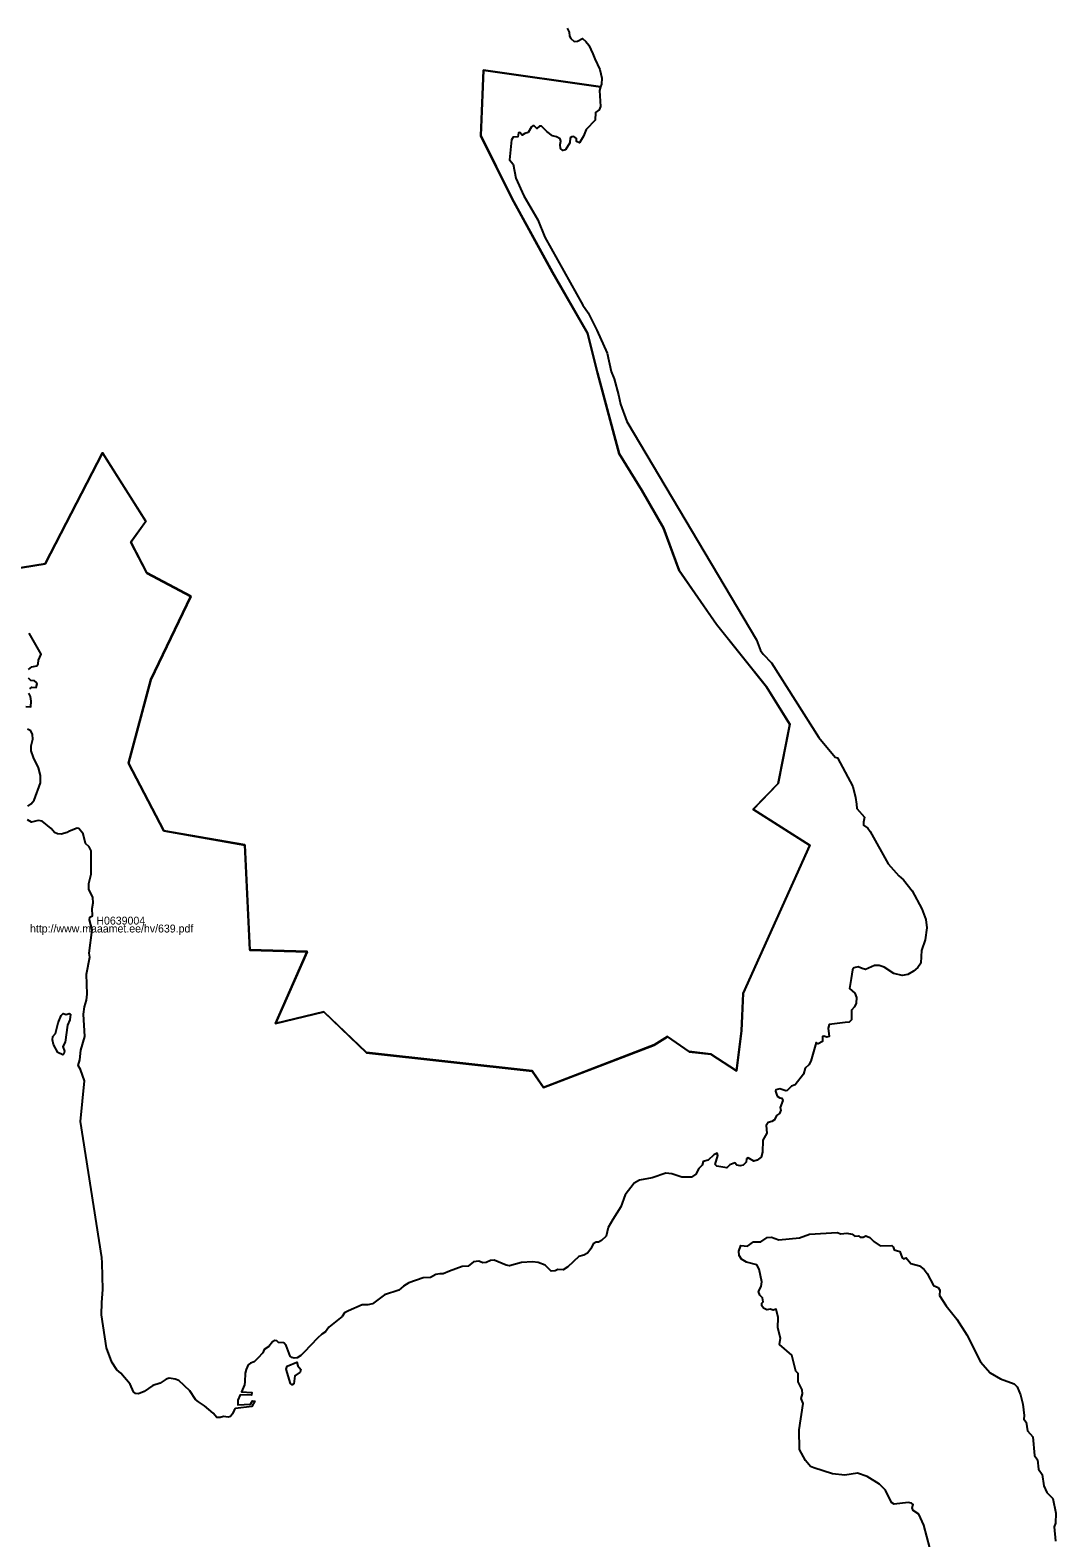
# Model space of a CAD drawing. Extents: x 369010 to 739155, y 6377141 to 6634081.
# Drawn here: x 443413 to 446658, y 6520540 to 6525308 of the extents above; entities that cross this region are included whole.
import ezdxf

# ---------------------------------------------------------------- set-up
doc = ezdxf.new("R2010")
doc.units = 0
for name, color, linetype in [('H_LINK', 7, 'Continuous'), ('H_PIIR', 7, 'Continuous'), ('H_TUNNUS', 7, 'Continuous')]:
    doc.layers.add(name, color=color, linetype=linetype)

msp = doc.modelspace()

# ---------------------------------------------------------------- linework, layer by layer
at = {"layer": 'H_PIIR'}
for points in [[(445111.0814, 6525314.0065), (445117.4214, 6525301.8065), (445118.8915, 6525288.6365), (445122.7913, 6525280.8266), (445133.5214, 6525272.0465), (445144.2615, 6525272.5365), (445159.8715, 6525281.3165), (445171.0914, 6525272.0465), (445179.8714, 6525259.8465), (445192.8015, 6525233.0166), (445198.6514, 6525217.3966), (445214.7514, 6525182.7566), (445221.0915, 6525155.9165), (445220.1214, 6525137.3765), (445217.5751, 6525128.6817), (444846.5215, 6525181.3618), (444838.7514, 6524974.6419), (444936.2714, 6524776.8719), (445065.4214, 6524542.182), (445176.1114, 6524349.6819), (445207.7013, 6524224.5219), (445276.2314, 6523968.732), (445347.3915, 6523852.702), (445415.9113, 6523734.0419), (445465.9914, 6523599.5519), (445584.1214, 6523429.5319), (445742.2614, 6523231.7618), (445816.0514, 6523113.092), (445779.1514, 6522925.8719), (445700.0914, 6522844.122), (445879.3115, 6522730.7319), (445668.8414, 6522262.4918), (445663.5715, 6522143.8319), (445647.7514, 6522017.2518), (445566.0515, 6522069.9919), (445497.5314, 6522077.912), (445429.0014, 6522125.3719), (445386.8314, 6522099.0019), (445036.3013, 6521964.5119), (445000.8414, 6522016.772), (444476.3614, 6522074.7819), (444341.9414, 6522203.9919), (444189.0814, 6522167.0719), (444289.2315, 6522393.8619), (444107.3813, 6522399.1319), (444091.5614, 6522731.3919), (443835.9114, 6522776.2219), (443723.6913, 6522990.3819), (443794.8614, 6523254.0819), (443921.3614, 6523517.7819), (443781.6814, 6523591.6119), (443731.6014, 6523689.1819), (443779.0413, 6523755.1018), (443641.9914, 6523971.3419), (443460.1415, 6523620.6218), (443133.3214, 6523567.8819)], [(443133.29, 6523567.22), (443460.1101, 6523619.9599), (443641.96, 6523970.68), (443779.0099, 6523754.4399), (443731.57, 6523688.52), (443781.65, 6523590.95), (443921.33, 6523517.12), (443794.83, 6523253.42), (443723.6599, 6522989.72), (443835.88, 6522775.56), (444091.53, 6522730.73), (444107.3499, 6522398.47), (444289.2001, 6522393.2), (444189.05, 6522166.41), (444341.91, 6522203.33), (444476.33, 6522074.12), (445000.81, 6522016.1101), (445036.2699, 6521963.85), (445386.8, 6522098.34), (445428.97, 6522124.71), (445497.5, 6522077.2501), (445566.0201, 6522069.33), (445647.72, 6522016.5899), (445663.5401, 6522143.17), (445668.81, 6522261.8299), (445879.2801, 6522730.07), (445700.06, 6522843.4601), (445779.12, 6522925.21), (445816.02, 6523112.4301), (445742.23, 6523231.0999), (445584.09, 6523428.87), (445465.96, 6523598.89), (445415.8799, 6523733.38), (445347.3601, 6523852.0401), (445276.2, 6523968.0701), (445207.6699, 6524223.86), (445176.08, 6524349.02), (445065.39, 6524541.5201), (444936.24, 6524776.21), (444838.72, 6524973.98), (444846.4901, 6525180.6999), (445217.5437, 6525128.0198), (445214.23, 6525116.7046), (445216.67, 6525065.9646), (445213.02, 6525056.2046), (445201.3099, 6525046.9346), (445199.84, 6525022.5446), (445172.04, 6524993.2646), (445163.7399, 6524972.7747), (445150.5701, 6524951.7947), (445141.2999, 6524955.6946), (445141.2999, 6524965.4546), (445132.52, 6524971.3046), (445126.18, 6524970.3347), (445120.81, 6524966.9147), (445119.84, 6524951.7947), (445106.1801, 6524929.3447), (445098.37, 6524927.3946), (445090.0801, 6524933.7346), (445089.1, 6524946.4246), (445092.03, 6524956.1846), (445089.1, 6524964.4746), (445077.64, 6524969.8447), (445064.95, 6524973.2647), (445046.9, 6524987.4146), (445030.32, 6525004.4947), (445024.46, 6525004.0046), (445015.19, 6524996.6846), (445007.3899, 6525004.9847), (445002.51, 6525004.9847), (444998.61, 6525001.5647), (444988.3599, 6524983.9946), (444978.1201, 6524980.5846), (444968.8501, 6524975.2146), (444962.02, 6524983.9946), (444957.63, 6524982.5347), (444955.19, 6524970.8247), (444941.0399, 6524968.8746), (444935.67, 6524960.5747), (444929.33, 6524897.1447), (444941.0399, 6524883.9746), (444949.33, 6524840.0547), (444974.95, 6524783.9447), (445018.85, 6524707.8247), (445040.56, 6524652.6946), (445161.3, 6524437.9946), (445177.6399, 6524413.5947), (445205.4501, 6524359.4347), (445238.62, 6524286.2446), (445251.31, 6524228.1846), (445260.0899, 6524204.7547), (445273.9999, 6524154.9847), (445279.8501, 6524125.2247), (445300.34, 6524070.0846), (445710.38, 6523379.6647), (445723.07, 6523346.4846), (445731.85, 6523334.2846), (445757.7, 6523306.9647), (445907.4799, 6523070.7946), (445959.92, 6523009.3147), (445966.75, 6523006.3847), (446015.5301, 6522915.6247), (446023.34, 6522880.9846), (446026.75, 6522860.0046), (446027.73, 6522846.3346), (446052.61, 6522819.5047), (446049.19, 6522803.3946), (446049.68, 6522793.6446), (446062.8501, 6522784.3646), (446069.93, 6522773.6346), (446127.01, 6522671.1747), (446160.67, 6522633.6047), (446175.54, 6522620.9147), (446202.8599, 6522586.2647), (446233.6001, 6522529.1747), (446246.2801, 6522495.5146), (446249.6999, 6522469.6447), (446244.08, 6522431.1047), (446232.8599, 6522397.4346), (446231.8901, 6522378.8946), (446230.91, 6522357.9147), (446220.67, 6522343.7646), (446207.0101, 6522332.0546), (446189.45, 6522321.8046), (446171.39, 6522318.3846), (446145.54, 6522324.7346), (446114.8001, 6522344.7346), (446098.4599, 6522350.1046), (446084.31, 6522349.6147), (446055.04, 6522337.9046), (446044.7899, 6522340.3446), (446032.6, 6522346.1947), (446018.9401, 6522342.7847), (446014.55, 6522336.9247), (446010.1599, 6522309.1146), (446004.79, 6522277.8846), (446021.38, 6522262.7546), (446026.74, 6522248.6046), (446026.02, 6522230.5546), (446020.6501, 6522219.3347), (446010.8901, 6522208.5946), (446011.3799, 6522178.3447), (446004.06, 6522170.5346), (445990.89, 6522169.5646), (445940.16, 6522163.7046), (445937.23, 6522152.4847), (445940.16, 6522126.1346), (445932.8399, 6522123.6946), (445923.57, 6522126.6246), (445919.6701, 6522125.1647), (445919.6701, 6522110.0346), (445905.52, 6522102.7147), (445899.66, 6522106.6146), (445882.59, 6522048.0647), (445876.4901, 6522036.3547), (445864.7799, 6522025.1346), (445859.42, 6522006.1046), (445832.5901, 6521972.9247), (445821.36, 6521968.5346), (445807.6999, 6521954.8646), (445803.31, 6521953.8947), (445784.29, 6521960.2347), (445772.09, 6521956.8247), (445770.63, 6521952.9146), (445776.4799, 6521937.3047), (445784.29, 6521931.9347), (445791.1201, 6521930.4746), (445793.56, 6521923.1546), (445785.95, 6521900.9247), (445787.96, 6521892.2447), (445783.73, 6521882.2346), (445774.1699, 6521875.3447), (445767.2699, 6521861.7746), (445759.14, 6521856.4347), (445747.58, 6521853.3146), (445741.13, 6521843.9746), (445743.1301, 6521820.1747), (445730.57, 6521798.1447), (445730.12, 6521760.1047), (445725.9001, 6521744.3146), (445712.78, 6521734.5246), (445702.0999, 6521731.8547), (445683.86, 6521742.0847), (445679.19, 6521738.5246), (445678.08, 6521728.2947), (445668.96, 6521719.1747), (445658.8399, 6521716.7247), (445647.9401, 6521718.7346), (445641.71, 6521726.5147), (445626.14, 6521719.3946), (445617.02, 6521710.2746), (445584.65, 6521715.3946), (445579.98, 6521721.3947), (445588.65, 6521748.9847), (445586.2101, 6521756.7646), (445575.53, 6521751.8747), (445557.2899, 6521734.7447), (445542.3901, 6521730.2946), (445539.16, 6521718.7246), (445528.04, 6521707.8246), (445518.25, 6521690.6947), (445505.13, 6521681.1247), (445473.87, 6521680.6846), (445442.73, 6521691.5846), (445424.0501, 6521693.5847), (445380.33, 6521678.6847), (445340.19, 6521671.7947), (445323.7401, 6521662.0047), (445295.4901, 6521624.6346), (445281.14, 6521587.4847), (445255.5599, 6521546.9946), (445241.2201, 6521521.6347), (445234.55, 6521494.4946), (445220.09, 6521480.4746), (445210.5299, 6521475.3646), (445203.41, 6521475.1447), (445193.52, 6521469.8047), (445186.18, 6521454.2247), (445176.17, 6521440.8847), (445164.16, 6521433.9847), (445148.1399, 6521429.7546), (445114.2201, 6521397.0547), (445098.6501, 6521388.1546), (445082.09, 6521389.0447), (445073.41, 6521384.1546), (445060.5099, 6521383.7046), (445041.83, 6521402.8347), (445020.2501, 6521410.8446), (445001.6799, 6521413.2947), (444967.2, 6521411.5147), (444929.27, 6521400.6047), (444918.82, 6521402.1646), (444880.9, 6521418.1746), (444869.11, 6521416.8447), (444855.54, 6521410.6146), (444844.8701, 6521410.3947), (444831.74, 6521415.5147), (444815.4001, 6521412.8446), (444798.0501, 6521399.0446), (444779.5901, 6521398.6046), (444739.44, 6521383.7046), (444718.9801, 6521375.4646), (444708.75, 6521375.4646), (444696.3999, 6521373.0147), (444679.5, 6521363.4546), (444656.37, 6521362.5647), (444610.88, 6521346.9947), (444593.53, 6521336.3146), (444578.63, 6521323.8647), (444533.59, 6521309.1746), (444495.45, 6521280.0347), (444480.99, 6521276.6946), (444462.7499, 6521277.1447), (444420.27, 6521258.6847), (444407.4801, 6521251.3346), (444399.47, 6521239.9946), (444357.0999, 6521206.8447), (444346.8701, 6521192.1646), (444335.7499, 6521184.6046), (444322.18, 6521171.9246), (444279.59, 6521126.9947), (444269.36, 6521116.5346), (444257.3499, 6521109.6446), (444248.01, 6521108.3046), (444240.6701, 6521110.5346), (444235.66, 6521114.9847), (444222.3101, 6521148.7946), (444215.42, 6521157.4746), (444197.8499, 6521158.1347), (444192.7299, 6521162.8147), (444187.17, 6521163.9247), (444179.05, 6521160.1346), (444167.4801, 6521145.0147), (444153.0301, 6521136.3347), (444148.3601, 6521125.8747), (444133.2299, 6521108.0847), (444121.44, 6521096.9646), (444110.1, 6521092.9547), (444102.43, 6521086.9446), (444095.7599, 6521072.9347), (444092.8699, 6521061.3647), (444092.2, 6521033.3346), (444090.6501, 6521024.4347), (444081.4201, 6521001.9647), (444114.3401, 6520999.7346), (444113.01, 6520991.2846), (444077.4201, 6520992.3946), (444069.8599, 6520976.1546), (444069.8599, 6520961.0347), (444110.12, 6520962.5847), (444116.5699, 6520973.2646), (444123.0201, 6520973.0447), (444114.12, 6520955.2447), (444062.62, 6520949.6846), (444058.17, 6520943.9046), (444052.6101, 6520932.1147), (444046.1599, 6520924.1047), (444038.8201, 6520922.3247), (444024.14, 6520923.8847), (444013.9101, 6520920.9947), (444003.13, 6520920.7746), (443991.79, 6520934.3447), (443964.65, 6520957.7046), (443945.3001, 6520969.9346), (443935.74, 6520978.1747), (443917.5099, 6521005.0846), (443882.7, 6521037.5747), (443871.14, 6521042.2447), (443852.67, 6521045.3546), (443842.5501, 6521042.0146), (443823.64, 6521029.1147), (443801.18, 6521021.9947), (443772.93, 6521002.6446), (443755.4701, 6520995.7446), (443746.1299, 6520996.8646), (443739.68, 6521002.1946), (443729.4501, 6521026.4446), (443699.5201, 6521061.1446), (443687.2899, 6521071.5947), (443670.83, 6521095.8447), (443654.26, 6521141.2246), (443638.7, 6521246.0047), (443639.13, 6521284.4846), (443642.59, 6521326.0847), (443639.9199, 6521409.9546), (443639.25, 6521426.4146), (443571.4101, 6521857.1146), (443584.0501, 6521985.5947), (443571.8499, 6522021.2146), (443564.5401, 6522033.4147), (443569.9, 6522051.9547), (443572.5901, 6522082.6947), (443585.2701, 6522125.1446), (443581.8601, 6522196.3846), (443585.03, 6522219.8047), (443590.8799, 6522240.3046), (443592.84, 6522259.3246), (443590.8799, 6522322.7646), (443601.3701, 6522375.9446), (443599.42, 6522389.6047), (443608.69, 6522462.7947), (443600.1599, 6522494.9946), (443601.62, 6522502.8046), (443609.4299, 6522506.7047), (443608.45, 6522530.6146), (443612.3501, 6522548.6747), (443611.38, 6522565.2646), (443597.72, 6522591.1246), (443598.2, 6522609.1746), (443606.0101, 6522638.9346), (443606.0101, 6522712.6147), (443599.18, 6522725.3047), (443587.23, 6522736.0346), (443580.4, 6522766.7747), (443566.2501, 6522783.3646), (443561.37, 6522784.3446), (443537.46, 6522774.5846), (443530.15, 6522770.6746), (443510.63, 6522765.3146), (443498.92, 6522766.7747), (443489.66, 6522770.6746), (443478.9199, 6522782.8746), (443450.1399, 6522806.7847), (443437.7, 6522808.7446), (443417.2099, 6522802.8846), (443404.5199, 6522811.1847)], [(443407.21, 6523286.4346), (443417.9401, 6523294.2347), (443433.5501, 6523297.1647), (443438.43, 6523303.5047), (443438.92, 6523315.2146), (443447.7, 6523334.2446), (443409.65, 6523400.6046)], [(443411.35, 6523224.4647), (443418.18, 6523230.3147), (443431.8401, 6523229.3446), (443435.2601, 6523240.5647), (443432.3301, 6523245.4446), (443425.9901, 6523249.8347), (443414.5301, 6523250.8146), (443407.7, 6523258.6146)], [(443399.16, 6523169.3246), (443414.28, 6523167.8647), (443416.2301, 6523185.4246), (443413.7899, 6523200.5546), (443408.43, 6523211.2847)], [(443405.5, 6522854.1247), (443415.26, 6522861.4447), (443425.5, 6522873.1547), (443445.4999, 6522927.3147), (443445.4999, 6522950.7346), (443438.92, 6522975.1247), (443423.31, 6523007.3346), (443415.4999, 6523029.2947), (443415.4999, 6523044.9047), (443421.3601, 6523065.3946), (443420.38, 6523080.5246), (443414.77, 6523092.2347), (443404.0401, 6523097.6047)], [(446268.4969, 6520472.5798), (446239.5337, 6520580.1573), (446224.1417, 6520614.9133), (446206.1018, 6520626.333), (446203.1228, 6520634.9392), (446205.7708, 6520645.3659), (446200.6403, 6520650), (446190.5445, 6520652.3171), (446146.0239, 6520647.0209), (446137.7487, 6520652.3171), (446118.7158, 6520691.2105), (446099.6827, 6520710.5745), (446060.4584, 6520733.9107), (446029.6747, 6520744.6683), (445989.9536, 6520738.2137), (445950.5636, 6520742.6823), (445891.8098, 6520761.3842), (445881.8795, 6520766.3494), (445865.1636, 6520785.3823), (445847.1237, 6520819.8072), (445845.6341, 6520881.3747), (445858.709, 6520964.9542), (445852.2542, 6520981.008), (445855.8954, 6520996.2343), (445854.9024, 6521007.9851), (445842.4896, 6521033.1418), (445842.4896, 6521059.7879), (445835.042, 6521067.2357), (445821.9671, 6521118.3763), (445783.4046, 6521152.1391), (445786.8801, 6521172.1652), (445777.943, 6521203.9419), (445778.936, 6521237.3737), (445773.3089, 6521263.0269), (445763.2131, 6521260.0477), (445753.945, 6521263.0269), (445743.5181, 6521261.3718), (445732.7605, 6521266.3369), (445727.4643, 6521274.4467), (445727.7952, 6521282.3909), (445731.7675, 6521286.5285), (445729.1193, 6521299.4377), (445720.8442, 6521307.2164), (445717.3685, 6521318.8017), (445724.9817, 6521335.5176), (445727.2988, 6521349.9164), (445718.6926, 6521389.8029), (445711.2448, 6521403.7053), (445679.4681, 6521412.477), (445663.2488, 6521421.9108), (445655.3045, 6521433.4959), (445654.9735, 6521446.9017), (445660.6006, 6521464.2797), (445681.9506, 6521462.2937), (445700.8181, 6521476.3616), (445724.8163, 6521476.3616), (445744.5112, 6521490.0983), (445757.9171, 6521491.0913), (445780.9221, 6521482.3196), (445847.1237, 6521489.2708), (445877.9074, 6521500.3596), (445966.1211, 6521506.3178), (445977.2098, 6521501.6836), (445996.2428, 6521503.3387), (446013.2897, 6521500.3596), (446021.2339, 6521494.0704), (446033.6467, 6521495.3945), (446038.2807, 6521491.0913), (446048.0455, 6521491.0913), (446056.8172, 6521495.0634), (446068.899, 6521490.2638), (446081.6429, 6521477.0236), (446101.6688, 6521463.9487), (446138.4108, 6521464.2797), (446143.2104, 6521460.3076), (446146.1893, 6521450.8738), (446163.7329, 6521445.5778), (446171.015, 6521425.8828), (446175.6491, 6521422.4072), (446184.4208, 6521425.5517), (446198.8196, 6521407.5118), (446226.7899, 6521400.0642), (446240.6921, 6521388.81), (446250.7879, 6521376.066), (446271.1449, 6521338.3313), (446284.8817, 6521331.5455), (446290.509, 6521323.6013), (446289.8469, 6521306.8855), (446311.0314, 6521274.1156), (446344.4632, 6521231.9122), (446375.909, 6521182.0954), (446419.6019, 6521096.8608), (446449.5582, 6521062.4359), (446482.4935, 6521043.0721), (446525.3591, 6521027.6801), (446535.2893, 6521018.0809), (446546.378, 6520992.2623), (446553.4947, 6520963.1335), (446557.9633, 6520926.7227), (446556.4738, 6520915.1375), (446564.2525, 6520906.3657), (446567.8937, 6520878.5611), (446584.9405, 6520859.8591), (446590.0712, 6520801.1052), (446600.1669, 6520787.3683), (446602.8149, 6520757.5777), (446613.9037, 6520740.1998), (446619.3653, 6520704.4508), (446629.13, 6520683.7629), (446648.4941, 6520664.3988), (446657.7623, 6520618.2233), (446656.9348, 6520586.4464), (446652.3007, 6520574.8613), (446656.6037, 6520530.0097)]]:
    msp.add_lwpolyline(points, dxfattribs=at)
for points in [[(443540.4945, 6522196.1384), (443538.5084, 6522178.4295), (443531.2262, 6522161.8791), (443523.7786, 6522107.7593), (443515.5034, 6522094.0225), (443520.965, 6522079.4581), (443519.4754, 6522071.183), (443515.5034, 6522067.2109), (443499.9459, 6522075.486), (443486.7058, 6522099.9806), (443482.8991, 6522115.0414), (443484.3887, 6522125.3026), (443492.6638, 6522134.5709), (443501.4355, 6522169.1613), (443511.2003, 6522192.1663), (443516.9929, 6522197.9589), (443526.2612, 6522195.642), (443536.0258, 6522198.4554)], [(444247.031, 6521027.6801), (444241.2384, 6521024.7012), (444236.6043, 6521028.0112), (444222.5364, 6521074.1867), (444225.5155, 6521083.1241), (444256.2992, 6521095.3713), (444259.6093, 6521084.7791), (444268.7121, 6521072.8628), (444266.7259, 6521064.753), (444250.3412, 6521052.6713)]]:
    msp.add_lwpolyline(points, close=True, dxfattribs=at)

# ---------------------------------------------------------------- texts
at = {"layer": 'H_LINK'}
msp.add_text('http://www.maaamet.ee/hv/639.pdf', height=25, rotation=360, dxfattribs=at).set_placement((443412.1517, 6522454.4947))
at = {"layer": 'H_TUNNUS'}
msp.add_text('H0639004', height=25, rotation=360, dxfattribs=at).set_placement((443622.1309, 6522479.4947))

doc.saveas('drawing.dxf')
